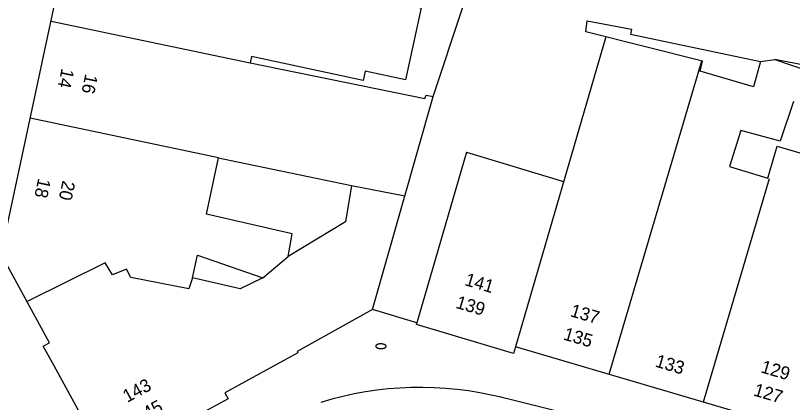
# Model space of a CAD drawing. Extents: x 81065 to 81486, y 452384 to 452681.
# Drawn here: x 81283.9 to 81331.82, y 452536.3 to 452560.19 of the extents above; entities that cross this region are included whole.
import ezdxf

# ---------------------------------------------------------------- set-up
doc = ezdxf.new("R2010")
doc.units = 0
for name, color, linetype in [('B-BH-AL-TOPOGRAFIE_HUISNUMMER-T25', 7, 'Continuous'), ('B-BH-KL-WATER_BRANDLEIDING_PUT-S', 7, 'Continuous'), ('B-BH-OG-TOPOGRAFIE_BEBOUWING-GV', 7, 'Continuous'), ('B-BH-OG-TOPOGRAFIE_BEBOUWING_PANDSCHEIDING-GV', 7, 'Continuous'), ('B-BH-VH-KANTOPSLUITING-GV', 7, 'Continuous')]:
    doc.layers.add(name, color=color, linetype=linetype)

msp = doc.modelspace()

# ---------------------------------------------------------------- linework, layer by layer
at = {"layer": 'B-BH-KL-WATER_BRANDLEIDING_PUT-S'}
msp.add_lwpolyline([(81306.441, 452539.916), (81306.407, 452539.915), (81306.374, 452539.913), (81306.342, 452539.909), (81306.31, 452539.904), (81306.28, 452539.897), (81306.252, 452539.889), (81306.226, 452539.88), (81306.202, 452539.869), (81306.181, 452539.857), (81306.162, 452539.845), (81306.147, 452539.831), (81306.135, 452539.817), (81306.126, 452539.803), (81306.121, 452539.788), (81306.119, 452539.772), (81306.121, 452539.757), (81306.126, 452539.742), (81306.134, 452539.727), (81306.146, 452539.713), (81306.161, 452539.699), (81306.18, 452539.686), (81306.201, 452539.674), (81306.224, 452539.663), (81306.25, 452539.654), (81306.279, 452539.645), (81306.308, 452539.638), (81306.34, 452539.632), (81306.372, 452539.628), (81306.405, 452539.625), (81306.439, 452539.624), (81306.472, 452539.625), (81306.506, 452539.627), (81306.538, 452539.631), (81306.57, 452539.636), (81306.6, 452539.643), (81306.628, 452539.651), (81306.654, 452539.66), (81306.678, 452539.671), (81306.699, 452539.682), (81306.717, 452539.695), (81306.733, 452539.708), (81306.745, 452539.723), (81306.754, 452539.737), (81306.759, 452539.752), (81306.761, 452539.767), (81306.759, 452539.783), (81306.754, 452539.798), (81306.746, 452539.813), (81306.734, 452539.827), (81306.719, 452539.841), (81306.7, 452539.853), (81306.679, 452539.866), (81306.656, 452539.877), (81306.63, 452539.886), (81306.601, 452539.895), (81306.571, 452539.902), (81306.54, 452539.908), (81306.508, 452539.912), (81306.475, 452539.915), (81306.441, 452539.916)], dxfattribs=at)
at = {"layer": 'B-BH-OG-TOPOGRAFIE_BEBOUWING-GV'}
for points in [[(81286.276, 452538.555), (81285.609, 452539.778), (81285.995, 452539.989), (81283.022, 452545.459), (81287.25, 452565.297), (81286.821, 452565.397), (81288.147, 452571.707), (81289.4, 452571.444), (81292.656, 452587.012), (81292.95, 452586.951), (81293.53, 452589.752), (81291.963, 452590.077), (81296.676, 452612.828), (81299.951, 452612.1), (81301.047, 452613.797), (81298.997, 452616.496), (81301.21, 452618.158)], [(81303.447, 452576.388), (81301.952, 452568.801), (81300.972, 452568.964), (81299.536, 452562.709), (81308.918, 452560.67), (81307.949, 452556.209), (81305.471, 452556.748), (81305.345, 452556.166), (81298.463, 452557.662), (81298.378, 452557.26), (81309.143, 452555.074), (81309.231, 452555.26), (81309.665, 452555.195), (81311.462, 452560.651), (81311.594, 452561.05), (81314.468, 452574.499), (81317.618, 452573.966)], [(81329.427, 452555.781), (81326.14, 452556.754), (81326.274, 452557.377), (81319.072, 452559.18), (81319.152, 452559.869), (81321.898, 452559.34), (81321.834, 452559.036), (81329.858, 452557.351), (81329.427, 452555.781)], [(81337.858, 452556.099), (81330.729, 452557.473), (81334.535, 452556.176)], [(81331.895, 452554.876), (81331.062, 452552.431), (81328.632, 452553.088), (81327.936, 452550.86), (81330.304, 452550.136), (81330.891, 452552.13), (81333.331, 452551.411)], [(81300.955, 452546.716), (81295.673, 452547.933), (81296.429, 452551.411), (81297.102, 452551.252), (81304.621, 452549.701), (81304.246, 452547.446), (81300.719, 452545.311), (81300.955, 452546.716)], [(81299.15, 452543.992), (81297.761, 452543.321), (81294.817, 452543.992), (81295.119, 452545.385), (81299.15, 452543.992)], [(81352.743, 452528.537), (81324.103, 452536.977), (81314.746, 452539.742), (81314.625, 452539.322), (81308.624, 452541.116), (81308.653, 452541.212), (81305.913, 452542.046), (81301.274, 452539.437), (81301.31, 452539.356), (81296.807, 452536.892), (81297.009, 452536.514), (81289.586, 452532.489), (81286.276, 452538.555)]]:
    msp.add_lwpolyline(points, dxfattribs=at)
at = {"layer": 'B-BH-OG-TOPOGRAFIE_BEBOUWING_PANDSCHEIDING-GV'}
for p, q in [((81286.089, 452559.847), (81298.378, 452557.26)), ((81320.307, 452558.871), (81314.745, 452539.741)), ((81320.517, 452538.037), (81326.239, 452557.386)), ((81329.858, 452557.351), (81330.729, 452557.473)), ((81305.913, 452542.046), (81309.665, 452555.195)), ((81296.429, 452551.411), (81284.81, 452553.849)), ((81311.719, 452551.759), (81308.653, 452541.212)), ((81311.719, 452551.759), (81317.711, 452549.941)), ((81330.383, 452550.112), (81326.326, 452536.322)), ((81304.621, 452549.701), (81307.911, 452549.049)), ((81299.15, 452543.992), (81300.719, 452545.311))]:
    msp.add_line(p, q, dxfattribs=at)
msp.add_lwpolyline([(81294.817, 452543.992), (81294.582, 452543.306), (81291.003, 452544.009), (81290.746, 452544.526), (81289.874, 452544.176), (81289.438, 452544.919), (81284.61, 452542.538)], dxfattribs=at)
at = {"layer": 'B-BH-VH-KANTOPSLUITING-GV'}
for centre, radius, start, end in [((81308.853, 452516.548), 20.68, 75.7873, 107.2375), ((81247.919, 452262.237), 282.189, 74.5452, 76.47676)]:
    msp.add_arc(centre, radius, start, end, dxfattribs=at)

# ---------------------------------------------------------------- texts
at = {"layer": 'B-BH-AL-TOPOGRAFIE_HUISNUMMER-T25'}
for s, rotation, p in [('14', 257.9688, (81286.752, 452556.963)), ('16', 257.9688, (81288.211, 452556.614)), ('18', 257.9688, (81285.307, 452550.183)), ('20', 257.9688, (81286.809, 452550.036)), ('141', 343.5819, (81311.56, 452543.549)), ('139', 343.5819, (81311.007, 452542.147)), ('137', 343.5819, (81318.066, 452541.632)), ('135', 343.5819, (81317.645, 452540.192)), ('133', 343.5819, (81323.308, 452538.523)), ('129', 343.5819, (81329.819, 452538.168)), ('143', 28.468, (81290.785, 452536.268)), ('127', 343.5819, (81329.373, 452536.736)), ('145', 28.468, (81291.5, 452534.949))]:
    msp.add_text(s, height=0.8, rotation=rotation, dxfattribs=at).set_placement(p)

doc.saveas('drawing.dxf')
